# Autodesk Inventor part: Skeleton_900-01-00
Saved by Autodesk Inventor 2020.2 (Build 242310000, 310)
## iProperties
Created: 2015-10
Part Number: Skeleton_900-01-00
Material: Ogólny
Document SubType Name: Modeling
Designer: F.Stasiak
Density: 1 g/cm^3
Appearance: Domyślna
Catalog Web Link: www.expertbooks.pl
Manager: www.cadconsulting.pl
Company: Fabian Stasiak CAD Consulting
_SkeletonDoc: Frame Skeleton File
_Version: 15.0.0
Author: F.Stasiak
Subject: Zbiór ćwiczeń. Autodesk Inventor 2020. Kurs Professional
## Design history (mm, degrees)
sketch "Szkielet odniesienia"
